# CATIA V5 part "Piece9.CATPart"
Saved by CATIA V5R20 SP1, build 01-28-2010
Part number: Bati1
Bounding box of the stored display mesh (mm): x -29 to 21, y -50 to 90.453, z -155 to 165
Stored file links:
  F:\TRAV\IAO\Exercice IAO\Catia\Piece9.CATPart
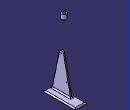
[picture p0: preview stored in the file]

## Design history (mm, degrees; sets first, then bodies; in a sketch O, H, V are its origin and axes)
Body1 (main body)
  Plane1: stored without definition
  Point1 "A": stored without definition
  Point2 "A": stored without definition
  Point3 "K": stored without definition
  Point4 "A": stored without definition
  Sketch1 on Plane1, origin (-9, 0, 0), H (0, 1, 0), V (0, 0, 1)
    point P1 (40, -150)
    line L1 (40, -150) -> (8.8388, 1.8142)
    arc A1 centre (0, 0) radius 9.0231 from (8.8388, 1.8142) to (-8.8388, 1.8142) ccw
    line L2 (-8.8388, 1.8142) -> (-40, -150)
    point P5 (-40, -150)
    line L3 (-40, -150) -> (40, -150)
    reference projected point E1 (0, 0) from Point1
    axis line L4 (0, -101.6977) -> (0, -210.239)
    point P6 (0, -101.6977)
    reference projected point E2 (0, 0) from Point2
    circle A2 centre (20, -100) radius 2
    point P8 (20, -100)
    reference projected point E3 (20, -100) from Point3
    circle A3 centre (0, 0) radius 1.9526
    point P9 (0, 0)
    reference projected point E4 (0, 0) from Point4
    distance L3 E2 = 150
    length L3 = 80
    radius A2 = 2
    radius A3 = 1.9526
    tangency: A1 L1, L2 A1
    horizontal: L3 H
    concentricity: A1 E1
    coincidence: P6 V, E3 P8, E4 P9
    vertical: L4 V
    symmetry: P5 P1 L4
  Pad1: profile Sketch1, direction (-1, 0, 0), length 5
  Sketch2 on face of Pad1 from Sketch1.L3, origin (0, 0, -150), H (1, 0, 0), V (0, -1, 0)
    line L1 (-29, 50) -> (21, 50)
    line L2 (21, 50) -> (21, -90.4526)
    line L3 (21, -90.4526) -> (-29, -90.4526)
    line L4 (-29, -90.4526) -> (-29, 50)
    reference projected line E1 (-9, 40) -> (-9, -40) from edge [face of Pad1 from Sketch1.L3 | start face of Pad1]
    reference projected line E2 (-9, 40) -> (-14, 40) from edge [face of Pad1 from Sketch1.L2 | face of Pad1 from Sketch1.L3]
    reference projected line E3 (-9, -40) -> (-14, -40) from edge [face of Pad1 from Sketch1.L3 | face of Pad1 from Sketch1.L1]
    reference projected line E4 (-9, -40) -> (-14, -40) from edge [face of Pad1 from Sketch1.L3 | face of Pad1 from Sketch1.L1]
    reference projected line E5 (-9, 40) -> (-14, 40) from edge [face of Pad1 from Sketch1.L2 | face of Pad1 from Sketch1.L3]
    reference projected line E6 (-9, -40) -> (-14, -40) from edge [face of Pad1 from Sketch1.L3 | face of Pad1 from Sketch1.L1]
    length L1 = 50
    distance E1 L4 = 20
    distance E5 L1 = 10
    distance E6 L3 = 50.4526
    vertical: L2 V, L4 V
    parallelism: E2 L1, L1 E3, E4 L3
  Pad2: profile Sketch2, direction (0, 0, -1), length 5
  Plane2 "Plan_ref": stored without definition
  Fillet1: radius 5, on start face of Pad2
  Line1: stored without definition
  DatumPoint1
  Line2: stored without definition
  Sketch3 on Plane2, origin (0, 0, 0), H (0, 1, 0), V (0, 0, 1)
    line L1 (25, 165) -> (30, 165)
    line L2 (30, 165) -> (30, 145)
    line L3 (30, 145) -> (25, 145)
    line L4 (25, 145) -> (25, 165)
    reference projected line E1 (20, 100) -> (20, 150) from Line1
    reference projected point E2 (20, 150) from vertex of DatumPoint1
    distance E1 L4 = 5
    length L3 = 5
    length L2 = 20
    distance E2 L3 = 5
    horizontal: L1 H, L3 H
    vertical: L2 V, L4 V
  Shaft1: profile Sketch3, axis Line2, angle 360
